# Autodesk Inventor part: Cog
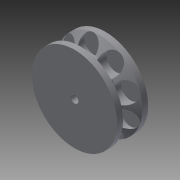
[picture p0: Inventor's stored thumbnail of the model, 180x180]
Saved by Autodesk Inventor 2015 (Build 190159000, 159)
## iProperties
Created: 2015-09
Part Number: Cog
Material: Generic
Document SubType Name: Modeling
Designer: Thomas
Density: 1 g/cm^3
Appearance: Default
Author: Thomas
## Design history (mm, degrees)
sketch "Sketch1"
  geometry: L1 (15.4, 0)-(-15.4, 0) reference; L2 (0, -15.4)-(0, 15.4) reference; C1 r 11 at (0, 0); C2 r 2.5 at (8.5, 0); C3 r 2.5 at (6.511, 5.464); C4 r 2.5 at (1.476, 8.371); C5 r 2.5 at (-4.25, 7.361); C6 r 2.5 at (-7.987, 2.907); C7 r 2.5 at (-7.987, -2.907); C8 r 2.5 at (-4.25, -7.361); C9 r 2.5 at (1.476, -8.371); C10 r 2.5 at (6.511, -5.464); C11 r 0.95 at (0, 0); 1 further point
  constraints: 11 centre point, 2 coincident, 1 point on line, 19 other
  dimensions: "d0" = 22 diameter of C1; "d1" = 5 diameter of C2; "d2" = 8.5 distance from line of L2 C2.centre; "d5" = 360 deg dimension on point (0, 0) C2.centre (derived); "d10" = 1.9 diameter of C11
extrude "Extrusion2" new body sketch "Sketch1" distance "d11" = 5; taper "d12" = 0 deg
sketch "Sketch2"
  geometry: C1 r 1 at (0, 0); C2 r 11 at (0, 0); 1 further point
  constraints: 2 centre point, 2 coincident
  dimensions: "d13" = 22 diameter of C2
extrude "Extrusion3" join sketch "Sketch2" distance "d14" = 1.5; taper "d15" = 0 deg
sketch "Sketch3"
  geometry: C1 r 1 at (6.511, 5.464); C2 r 11 at (6.511, 5.464); 1 further point
  constraints: 2 centre point, 2 coincident
extrude "Extrusion4" join sketch "Sketch3" distance "d16" = 1.5; taper "d17" = 0 deg
workplane "Work Plane2"
  workplane "Work Plane1"
sketch "Sketch4"
  geometry: L1 (11, -1.5)-(11, 6.5) reference; L2 (-11, -1.5)-(11, -1.5) reference; L3 (11, 6.5)-(-11, 6.5) reference; L4 (11, 0)-(11, 5); L5 (11, 5)-(7.5, 2.5); L6 (7.5, 2.5)-(11, 0); L7 (0, -3.1)-(0, 8.1) reference; 3 further points
  constraints: 6 end point, 2 point on line
  dimensions: "d19" = 5 distance of L4.start L4.end; "d21" = 3.5 distance from line of L5.end L1; "d22" = 4 distance from line of L5.end L2
revolve "Revolution1" sketch "Sketch4" stored, may be unused: angle "d23" = 90 deg
fillet "Fillet1" dims "d24" = 0.5
body "Solid2"
other parameters: "d18" = -11
